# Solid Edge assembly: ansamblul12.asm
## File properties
Author: user
Template: Iso Assembly.asm
Last saved by: user
Revision: 8
Application: Solid Edge
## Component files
beton.par
stalp.par
bec.par
ornament.par
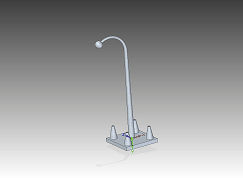
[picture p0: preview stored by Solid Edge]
